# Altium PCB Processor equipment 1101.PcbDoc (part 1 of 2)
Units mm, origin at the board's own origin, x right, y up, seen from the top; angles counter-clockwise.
Board outline 129 x 113 mm, 4 copper layers (Top Layer, Signal Layer 1, Signal Layer 2, Bottom Layer), stack 0.778 mm thick; 199 components, 116 nets, 557 pads, 191 vias.
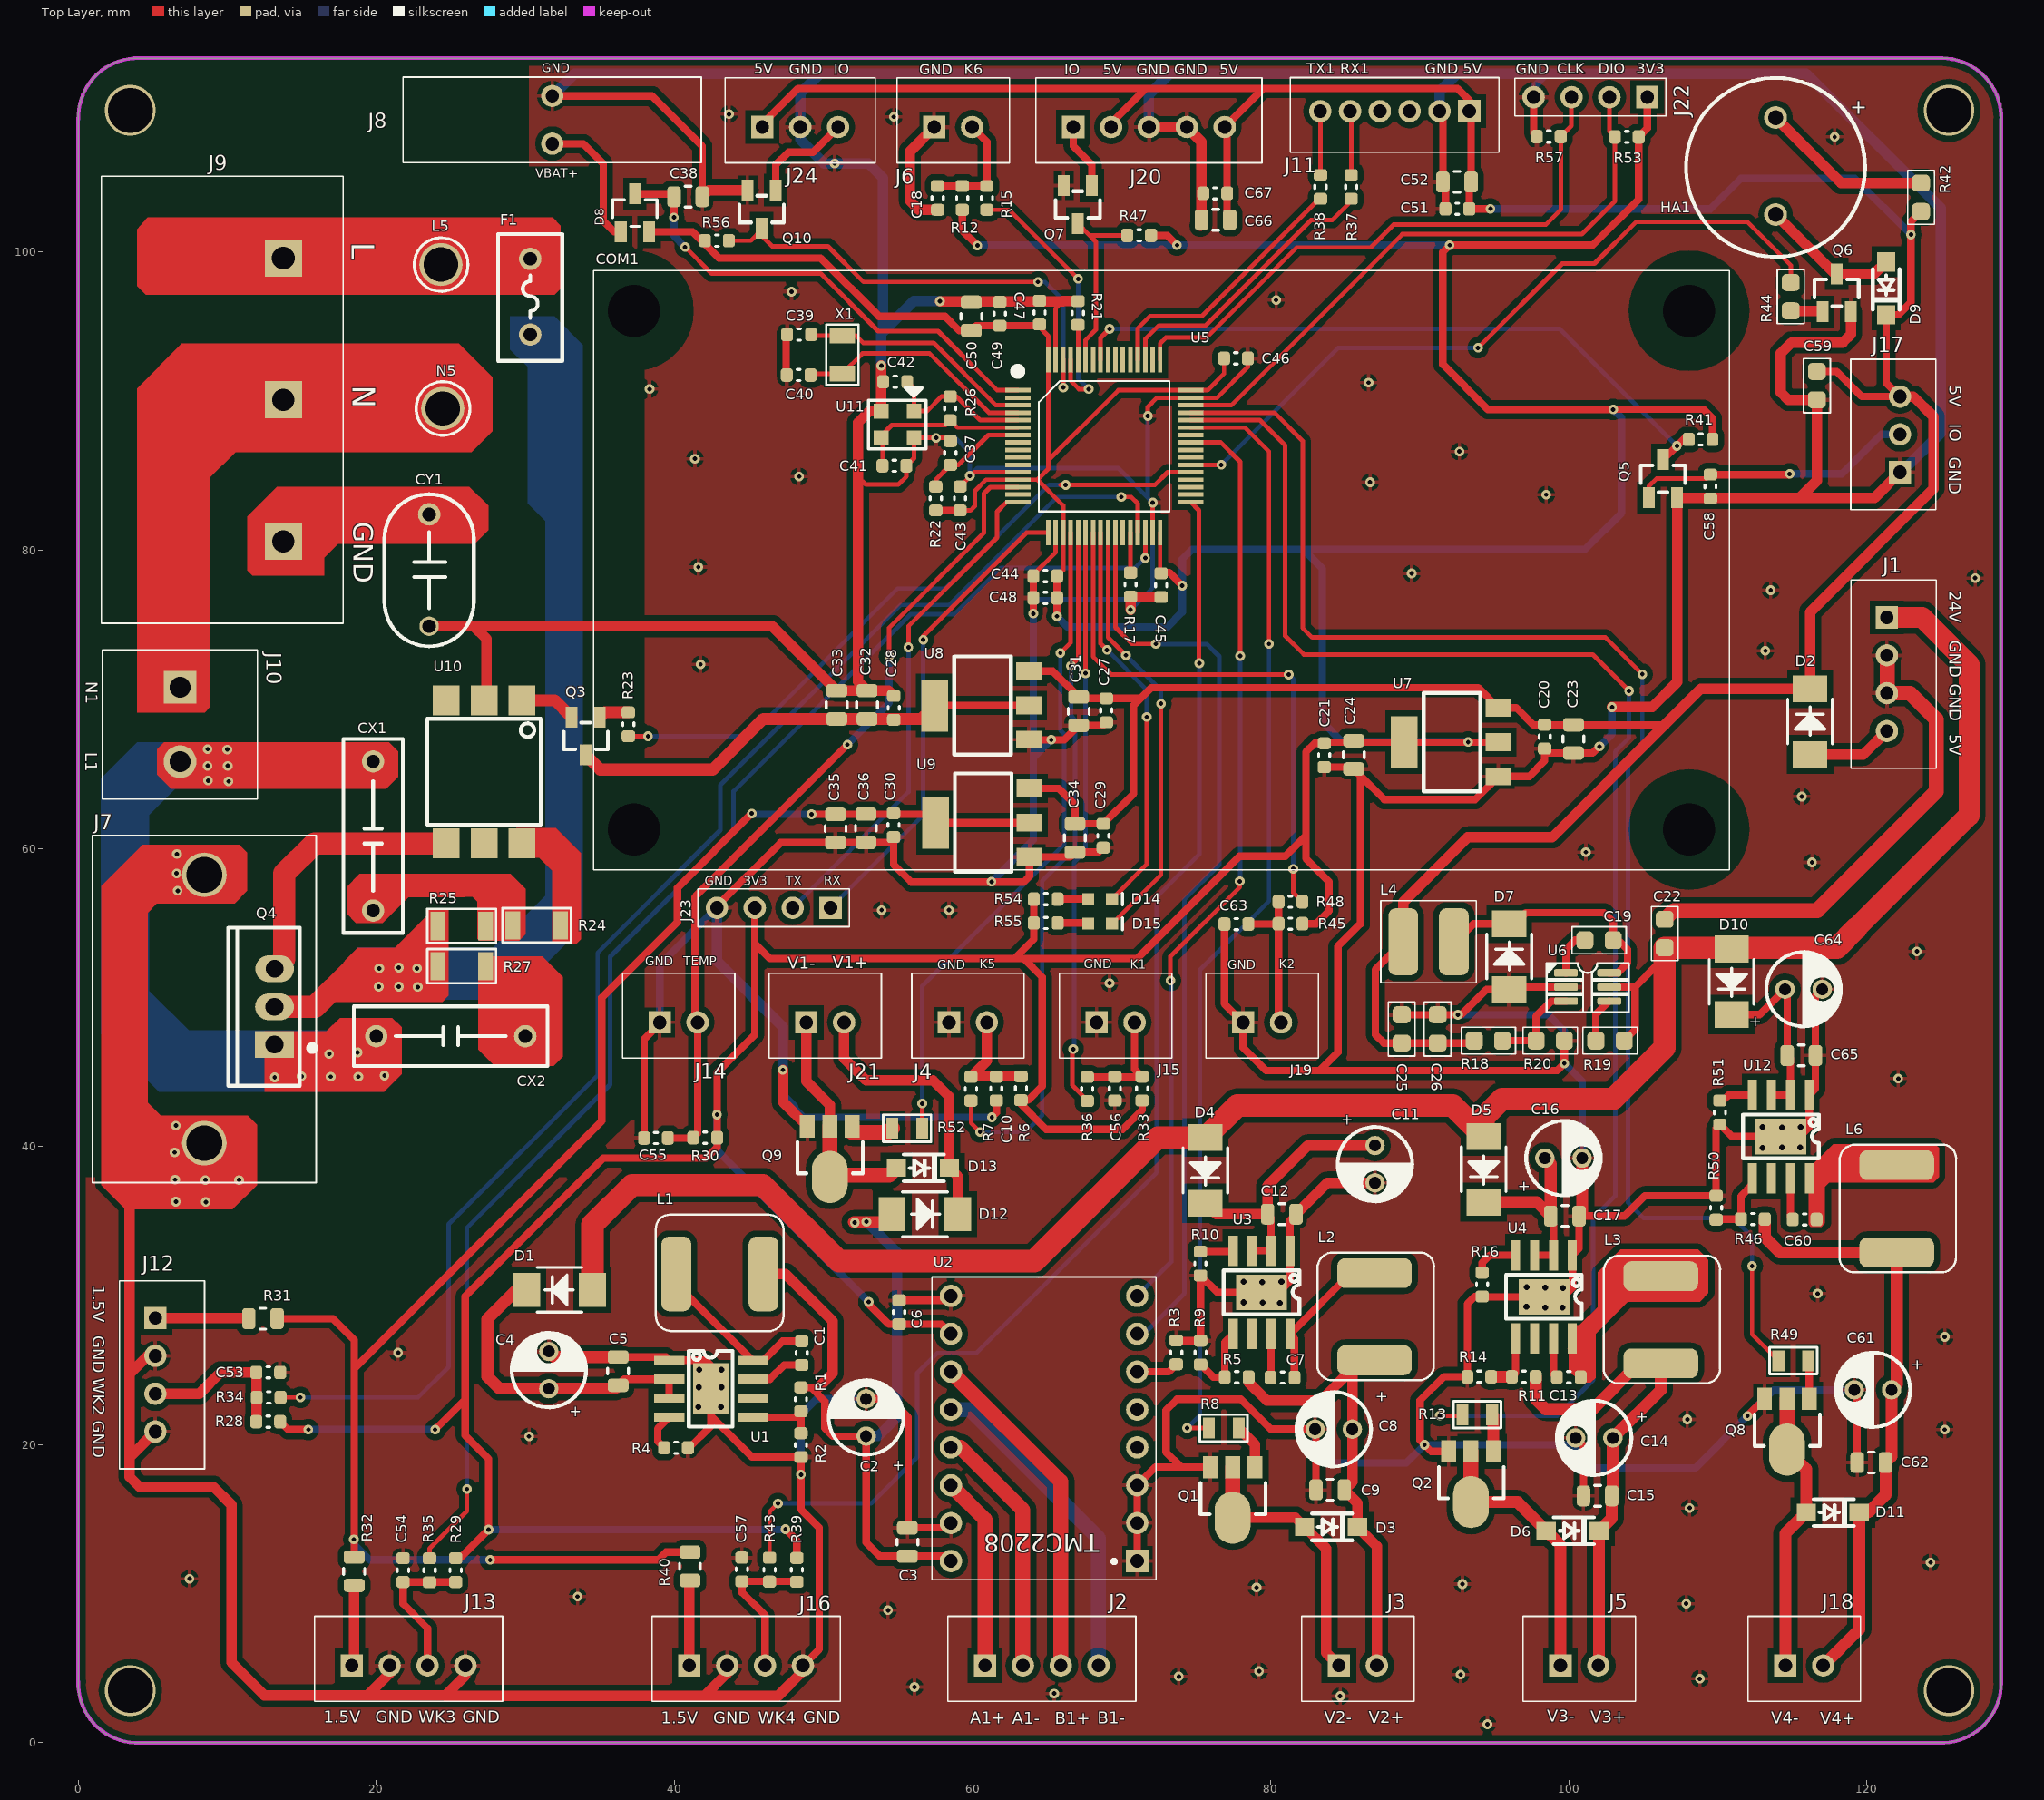
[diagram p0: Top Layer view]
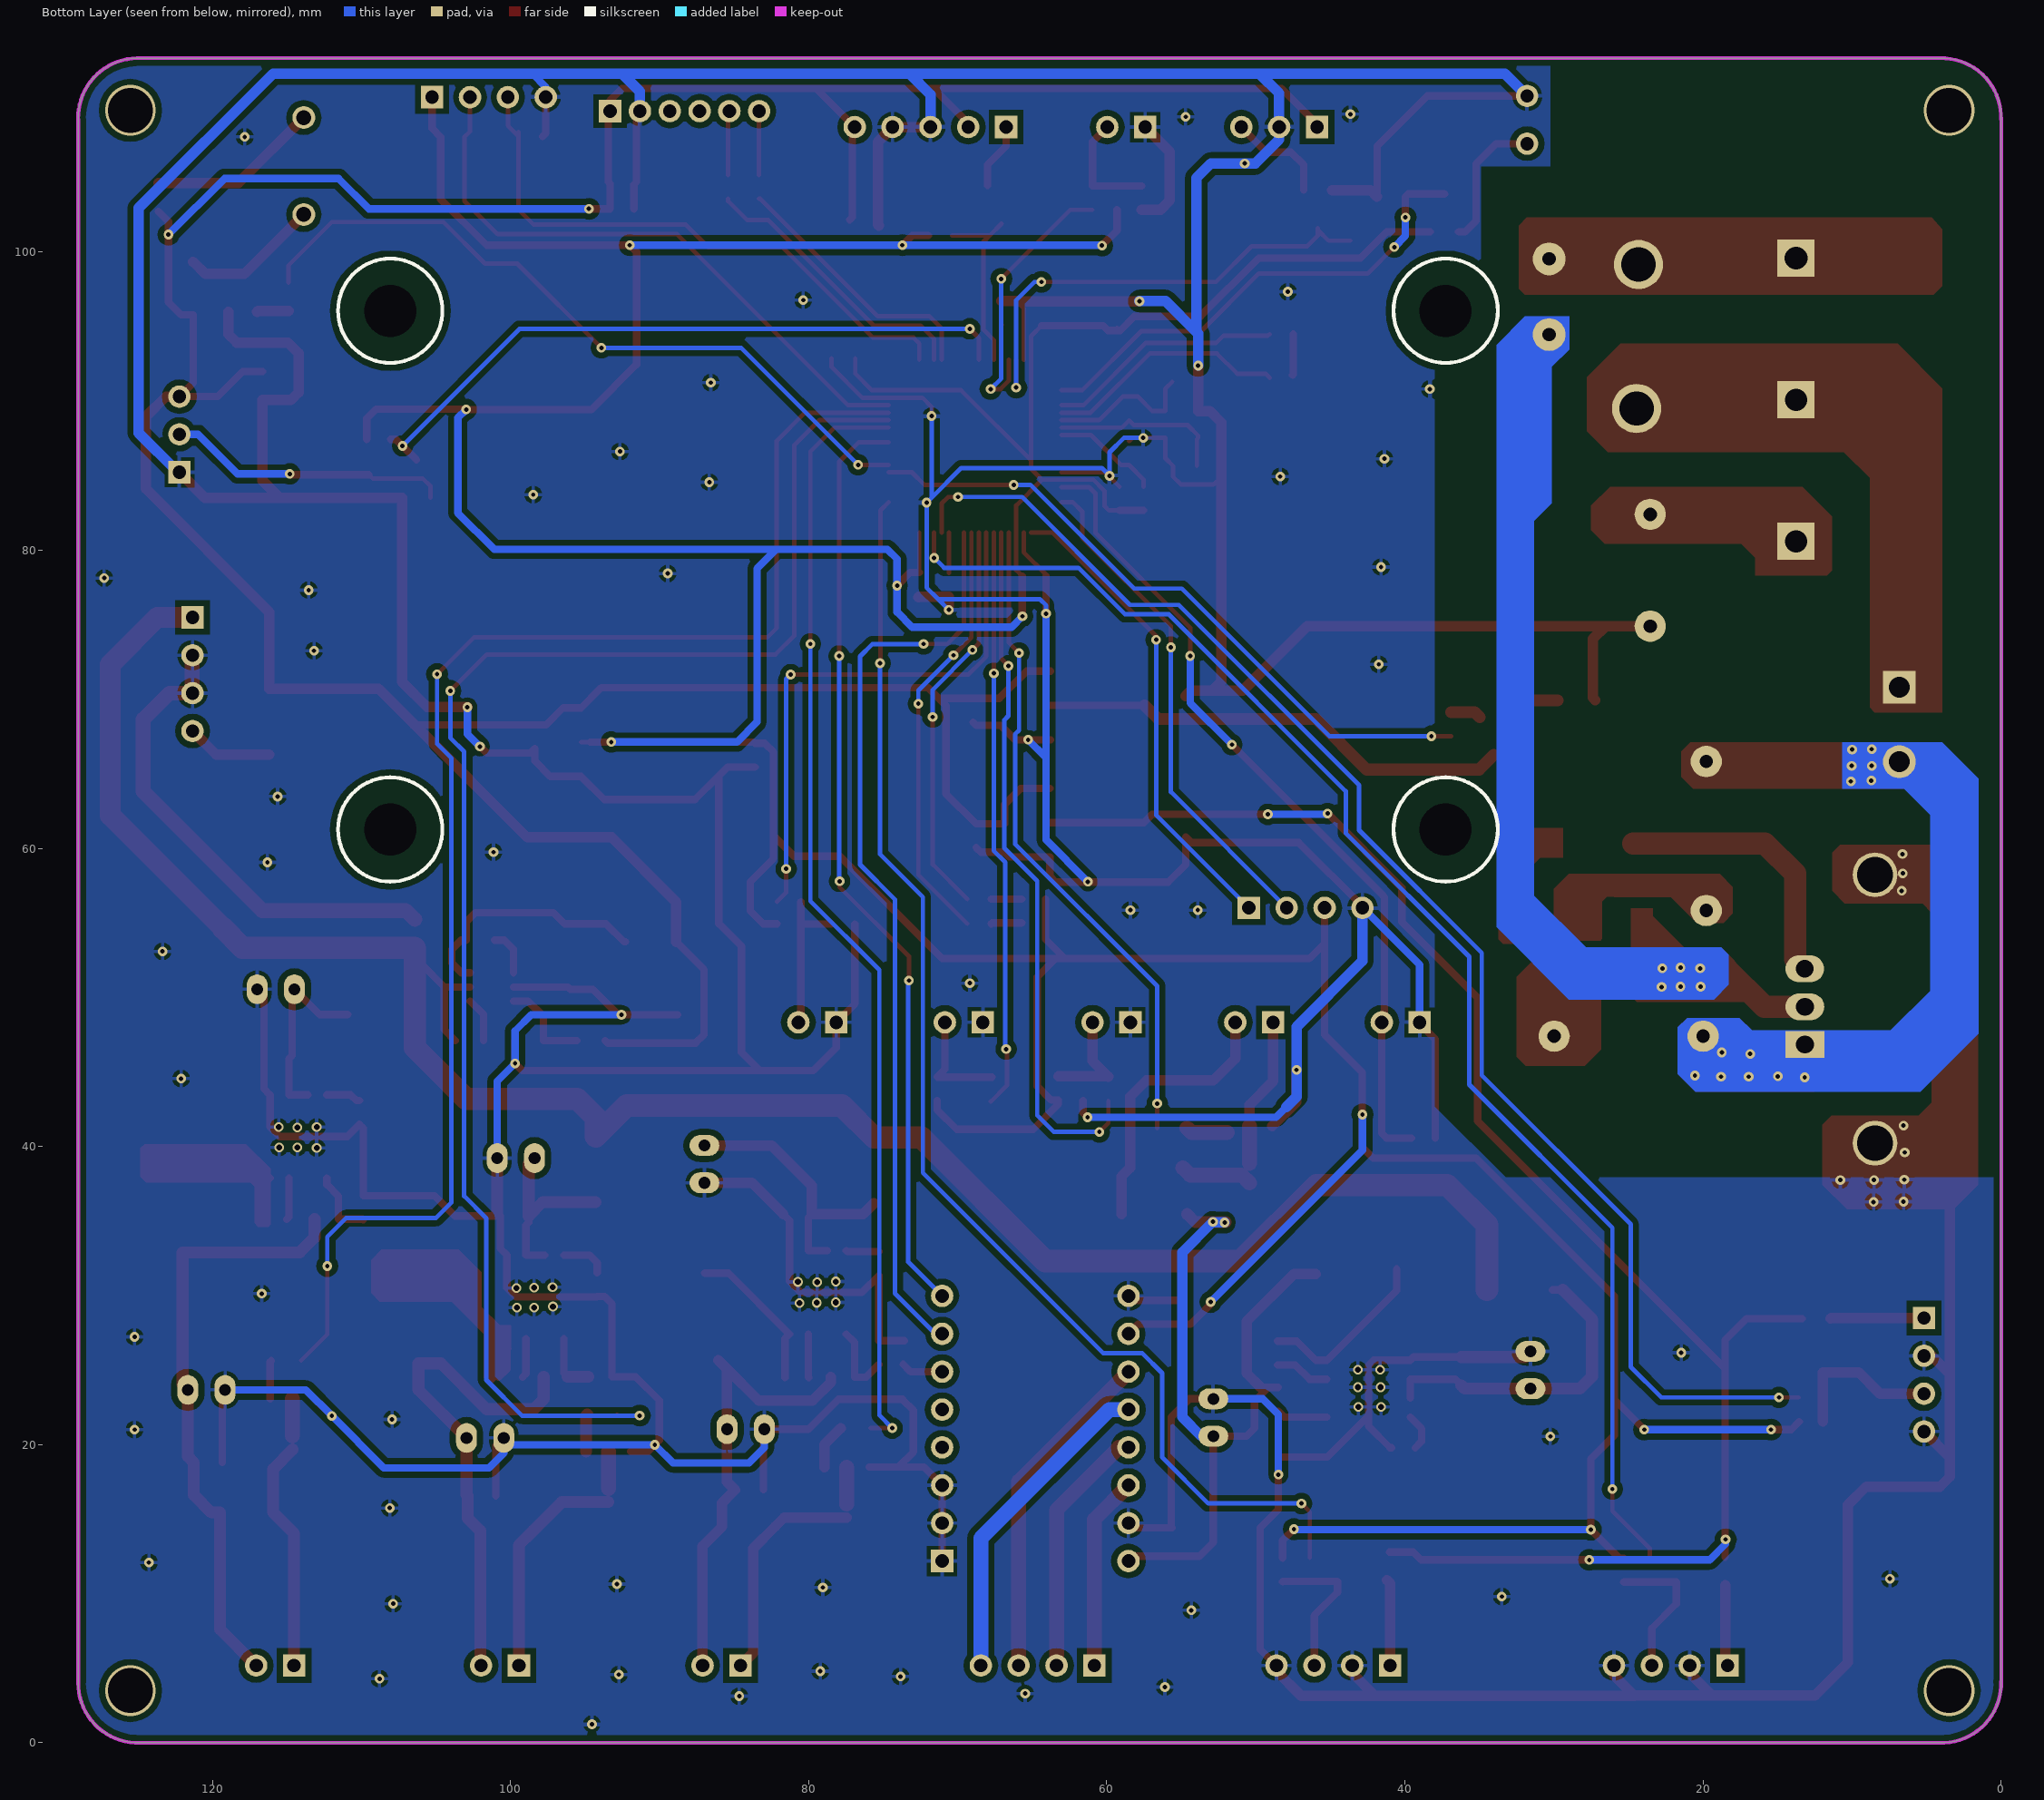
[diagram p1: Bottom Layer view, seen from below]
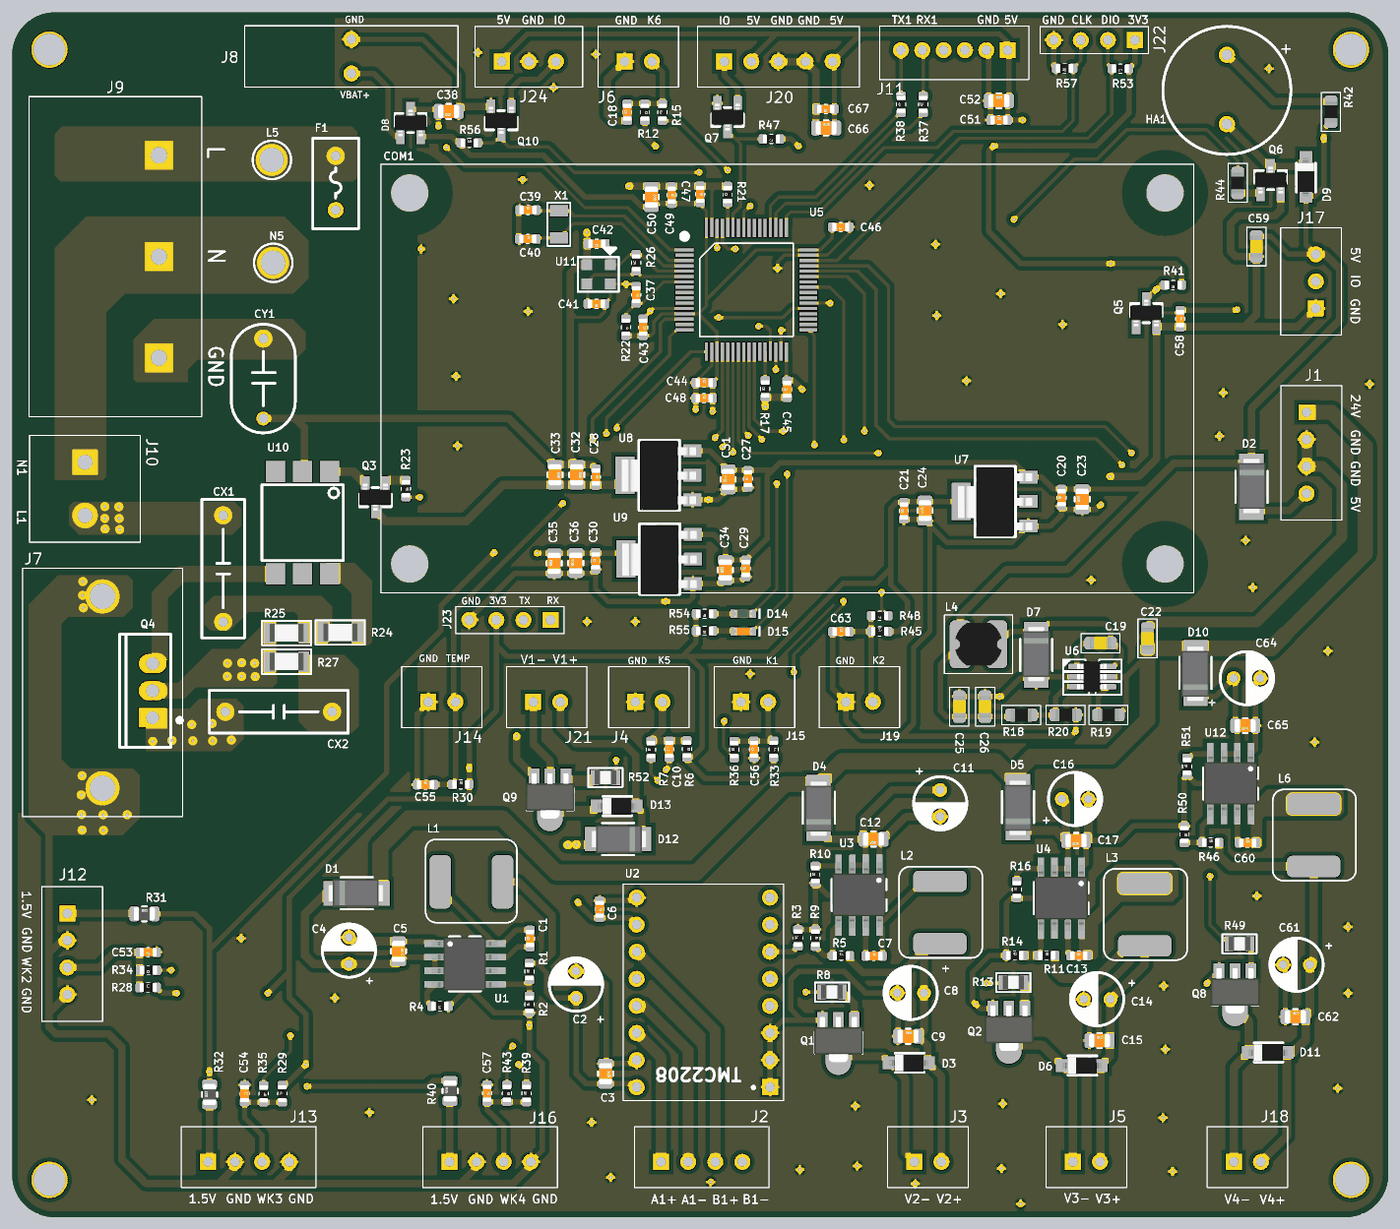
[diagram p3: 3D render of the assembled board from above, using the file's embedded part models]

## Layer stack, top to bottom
Top Solder: solder mask 0.0102, Solder Resist, Dk 3.5
Top Layer: signal copper 0.0356
Dielectric1: core 0.254, FR-4, Dk 4.2
Signal Layer 1: signal copper 0.036
Dielectric2: prepreg 0.127, Dk 4.2
Signal Layer 2: signal copper 0.036
Dielectric3: core 0.254, Dk 4.2
Bottom Layer: signal copper 0.0356
Bottom Solder: solder mask 0.0102, Solder Resist, Dk 3.5

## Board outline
3.807,0 cw(c3.998,3.991) 0.004,4.112 0,4.112 0,108.882 0.009,108.882 cw(c3.999,109.009) 4.089,113 125.063,113 cw(c125.005,109) 129.004,108.917 129,108.917 129,4.039 cw(c124.998,4) 124.852,0

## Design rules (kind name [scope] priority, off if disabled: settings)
Clearance [All] p1: gap=0.4
FabricationTestpoint [(IsPad And (OnTopLayer Or OnBottomLayer))] p1: side=3 testpointundercomponent=TRUE minsize=1.016 maxsize=2.54 preferedsize=1.524 minholesize=0 maxholesize=1.016 preferedholesize=0.813 testpointgrid=0.025 allowsidetop=TRUE allowsidebottom=TRUE usegrid=TRUE gridtolerance=0
PolygonConnect [All] p1: connectstyle=Relief reliefconductorwidth=0.254 reliefentries=4 polygonreliefangle="90 Angle" airgapwidth=0.254
RoutingVias [All] p1: holewidth=0.711 width=1.27 viastyle="Through Hole" minholewidth=0.711 minwidth=1.27 maxholewidth=0.711 maxwidth=1.27
SolderMaskExpansion [All] p1: expansion=0.102
Width [All] p1: maxlimit=5 minlimit=0.254 preferedwidth=0.254
29 further rules are at their usual default settings.

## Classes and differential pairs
component class "Processor equipment drive 1007": C51 C52 C53 C54 C55 C56 C57 C58 C59 C60 C61 C62 C63 C64 C65 C66 C67 D9 D10 D11 D12 D13 D14 D15 HA1 J11 J12 J13 J14 J15 J16 J17 J18 J19 J20 J21 J22 J23 J24 L6 Q5 Q6 Q7 Q8 Q9 Q10 Q11 R28 R29 R30 R31 R32 R33 R34 R35 R36 R37 R38 R39 R40 R41 R42 R43 R44 R45 R46 R47 R48 R49 R50 R51 R52 R53 R54 R55 R56 R57 U12
component class "Processor equipment control 1007": C19 C20 C21 C22 C23 C24 C25 C26 C27 C28 C29 C30 C31 C32 C33 C34 C35 C36 C37 C38 C39 C40 C41 C42 C43 C44 C45 C46 C47 C48 C49 C50 COM1 CX1 CX2 CY1 D7 D8 F1 J7 J8 J9 J10 L4 L5 N5 Q3 Q4 R17 R18 R19 R20 R21 R22 R23 R24 R25 R26 R27 U5 U6 U7 U8 U9 U10 U11 X1
component class "motor drive 1007": C1 C2 C3 C4 C5 C6 C7 C8 C9 C10 C11 C12 C13 C14 C15 C16 C17 C18 D1 D2 D3 D4 D5 D6 J1 J2 J3 J4 J5 J6 L1 L2 L3 Q1 Q2 R1 R2 R3 R4 R5 R6 R7 R8 R9 R10 R11 R12 R13 R14 R15 R16 U1 U2 U3 U4

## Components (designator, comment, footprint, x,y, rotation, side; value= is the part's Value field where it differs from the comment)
C1 "Capacitor NP" CAP_C_0603 48.539,26.137 r90 top locked
C2 "Capacitor POL" RB2.5/5_0.8 52.857,21.819 r270 top locked
C3 "Capacitor NP" CAP_C_0805 55.626,13.462 r270 top
C4 "Capacitor POL" RB2.5/5_0.8 31.572,24.999 r270 top locked
C5 "Capacitor NP" CAP_C_0805 36.22,24.928 r270 top locked
C6 "Capacitor NP" CAP_C_0603 55.067,28.88 r270 top
C7 "Capacitor NP" CAP_C_0603 80.795,24.496 r0 top locked
C8 "Capacitor POL" RB2.5/5_0.8 84.226,21.031 r0 top locked
C9 "Capacitor NP" CAP_C_0805 83.988,16.967 r0 top locked
C10 "Capacitor NP" CAP_C_0603 61.595,43.878 r90 top locked
C11 "Capacitor POL" RB2.5/5_0.8 86.995,38.811 r90 top locked
C12 "Capacitor NP" CAP_C_0805 80.747,35.458 r180 top locked
C13 "Capacitor NP" CAP_C_0603 99.997,24.521 r0 top locked
C14 "Capacitor POL" RB2.5/5_0.8 101.702,20.447 r0 top locked
C15 "Capacitor NP" CAP_C_0805 101.93,16.561 r0 top locked
C16 "Capacitor POL" RB2.5/5_0.8 99.639,39.218 r180 top locked
C17 "Capacitor NP" CAP_C_0805 99.736,35.331 r180 top locked
C18 "Capacitor NP" CAP_C_0603 57.658,103.632 r90 top locked
C19 "0.1uF" CAP_SMT_0805_T 102.027,53.833 r180 top locked
C20 "Capacitor NP" CAP_C_0603 98.374,67.488 r90 top locked
C21 "Capacitor NP" CAP_C_0603 83.591,66.243 r90 top locked
C22 "0.1uF" CAP_SMT_0805_T 106.426,54.28 r90 top locked
C23 "Capacitor NP" CAP_C_0805 100.305,67.335 r90 top locked
C24 "Capacitor NP" CAP_C_0805 85.573,66.269 r90 top locked
C25 "10uF" CAP_SMT_0805_T 88.788,47.884 r90 top locked
C26 "0.1uF" CAP_SMT_0805_T 91.201,47.884 r90 top locked
C27 "Capacitor NP" CAP_C_0603 68.971,69.251 r90 top locked
C28 "Capacitor NP" CAP_C_0603 54.712,69.418 r270 top locked
C29 "Capacitor NP" CAP_C_0603 68.768,60.843 r90 top locked
C30 "Capacitor NP" CAP_C_0603 54.697,61.555 r90 top locked
C31 "Capacitor NP" CAP_C_0805 67.117,69.2 r90 top locked
C32 "Capacitor NP" CAP_C_0805 52.923,69.626 r270 top locked
C33 "Capacitor NP" CAP_C_0805 50.891,69.626 r270 top locked
C34 "Capacitor NP" CAP_C_0805 66.863,60.691 r90 top locked
C35 "Capacitor NP" CAP_C_0805 50.81,61.326 r90 top locked
C36 "Capacitor NP" CAP_C_0805 52.842,61.351 r90 top locked
C37 "Capacitor NP" CAP_C_0603 58.507,86.51 r270 top locked
C38 "Capacitor NP" CAP_C_0805 40.919,103.708 r180 top
C39 "Capacitor NP" CAP_C_0603 48.362,94.463 r0 top locked
C40 "Capacitor NP" CAP_C_0603 48.336,91.745 r0 top
C41 "Capacitor NP" CAP_C_0603 54.76,85.659 r180 top locked
C42 "Capacitor NP" CAP_C_0603 54.811,91.298 r180 top locked
C43 "Capacitor NP" CAP_C_0603 59.157,83.464 r270 top locked
C44 "Capacitor NP" CAP_C_0603 64.872,78.257 r0 top locked
C45 "Capacitor NP" CAP_C_0603 72.644,77.648 r90 top locked
C46 "Capacitor NP" CAP_C_0603 77.673,92.862 r180 top locked
C47 "Capacitor NP" CAP_C_0603 64.491,95.936 r270 top locked
C48 "Capacitor NP" CAP_C_0603 64.872,76.797 r0 top locked
C49 "Capacitor NP" CAP_C_0603 61.824,95.86 r270 top
C50 "Capacitor NP" CAP_C_0805 59.919,95.682 r270 top
C51 "Capacitor NP" CAP_C_0603 92.52,102.895 r0 top locked
C52 "Capacitor NP" CAP_C_0805 92.497,104.699 r0 top locked
C53 "Capacitor NP" CAP_C_0603 12.751,24.841 r180 top locked
C54 "Capacitor NP" CAP_C_0603 21.793,11.582 r270 top locked
C55 "Capacitor NP" CAP_C_0603 38.76,40.564 r0 top locked
C56 "Capacitor NP" CAP_C_0603 69.545,43.879 r90 top locked
C57 "Capacitor NP" CAP_C_0603 44.526,11.62 r270 top
C58 "Capacitor NP" CAP_C_0603 109.499,84.264 r270 top locked
C59 "10uF" CAP_SMT_0805_T 116.637,91.034 r270 top locked
C60 "Capacitor NP" CAP_C_0603 115.811,35.103 r0 top locked
C61 "Capacitor POL" RB2.5/5_0.8 120.396,23.673 r0 top locked
C62 "Capacitor NP" CAP_C_0805 120.294,18.796 r0 top locked
C63 "Capacitor NP" CAP_C_0603 77.699,54.915 r0 top locked
C64 "Capacitor POL" RB2.5/5_0.8 115.748,50.546 r180 top locked
C65 "Capacitor NP" CAP_C_0805 115.595,46.101 r180 top locked
C66 "Capacitor NP" CAP_C_0805 76.302,102.159 r0 top
C67 "Capacitor NP" CAP_C_0603 76.276,103.937 r180 top
COM1 "HDR1X4" AC220v-24v 72.669,78.659 r180 top locked
CX1 "0.1UF 630V" C13*4*10_0.9 19.787,60.824 r90 top locked
CX2 "0.01UF 630V" C13*4*10_0.9 24.994,47.396 r180 top locked
CY1 "472" C9*6*7.5 23.546,78.65 r90 top locked
D1 "US1K" SMA-R 34.499,30.378 r180 top locked
D2 "US1K" SMA-R 116.18,66.294 r90 top locked
D3 "Diode Single" SOD123-R 82.271,14.478 r0 top locked
D4 "US1K" SMA-R 75.616,40.595 r270 top locked
D5 "US1K" SMA-R 94.285,40.665 r270 top locked
D6 "Diode Single" SOD123-R 98.476,14.224 r0 top locked
D7 "US1K" SMA-R 95.997,50.531 r90 top locked
D8 "BAT54C-7-F" SOT23-R-R 38.298,101.346 r270 top
D9 "Diode Single" SOD123-R 121.285,99.339 r270 top locked
D10 "US1K" SMA-R 110.922,53.244 r270 top locked
D11 "Diode Single" SOD123-R 115.926,15.443 r0 top locked
D12 "US1K" SMA-R 54.604,35.458 r0 top locked
D13 "Diode Single" SOD123-R 54.889,38.557 r0 top locked
D14 "LED_green" LED_0603_GREEN 68.555,56.591 r0 top locked
D15 "LED_red" LED_0603_RED 68.555,54.94 r0 top locked
F1 "6.3A/300V" FUSE_8.4*4.3_5.08_0.6 30.328,99.538 r270 top locked
HA1 "蜂鸣器" 蜂鸣器6.5mm 113.868,105.766 r270 top locked
J1 "HDR1X4" XH2.54mmX4P 121.336,71.679 r270 top locked
J2 "HDR1X4" XH2.54mmX4P 64.643,5.182 r0 top locked
J3 "2PIN" XH2.54mmX2P 85.845,5.182 r0 top locked
J4 "2PIN" XH2.54mmX2P 59.69,48.321 r0 top locked
J5 "2PIN" XH2.54mmX2P 100.704,5.182 r0 top locked
J6 "2PIN" XH2.54mmX2P 58.699,108.382 r0 top locked
J7 "2PIN" 散热器 8.469,49.22 r90 top locked
J8 "CR1220-2" CR2032-6 31.801,108.864 r90 top locked
J9 "3PIN" HB-9500-3P 13.767,90.089 r270 top locked
J10 "2PIN" DG/KF128-2P 6.833,68.307 r270 top locked
J11 "6PIN" HY2.0-6A 88.32,109.449 r180 top locked
J12 "HDR1X4" XH2.54mmX4P 5.182,24.685 r270 top locked
J13 "HDR1X4" XH2.54mmX4P 22.168,5.182 r0 top locked
J14 "2PIN" XH2.54mmX2P 40.284,48.321 r0 top locked
J15 "2PIN" XH2.54mmX2P 69.596,48.321 r0 top locked
J16 "HDR1X4" XH2.54mmX4P 44.809,5.182 r0 top locked
J17 "3PIN" XH2.54mm-3p 122.21,87.764 r90 top locked
J18 "2PIN" XH2.54mmX2P 115.792,5.182 r0 top locked
J19 "2PIN" XH2.54mmX2P 79.422,48.321 r0 top locked
J20 "Header 1x5" XH2.54MM-5P 71.831,108.382 r0 top locked
J21 "2PIN" XH2.54mmX2P 50.114,48.321 r0 top locked
J22 "HDR1X4" 2.54mmx4 105.258,110.388 r180 top locked
J23 "HDR1X4" 2.54mmx4 50.47,56.007 r180 top locked
J24 "3PIN" XH2.54mm-3p 48.438,108.382 r0 top locked
L1 "Inductor" 贴片电感 43.053,31.445 r180 top locked
L2 "Inductor" 贴片电感 86.97,28.579 r90 top locked
L3 "Inductor" 贴片电感 106.172,28.372 r90 top locked
L4 "100016336" 100016336_SS_B 90.589,53.731 r180 top locked
L5 "" PAD_1.8 24.333,99.157 r0 top locked
L6 "Inductor" 贴片电感 121.996,35.818 r90 top locked
N5 "" PAD_1.8 24.46,89.505 r0 top locked
Q1 "BCX56" SOT89-R-R#1 78.945,18.488 r90 top locked
Q2 "BCX56" SOT89-R-R#1 94.932,19.543 r90 top locked
Q3 "SS8050" SOT23-L-R 34.996,68.804 r90 top locked
Q4 "BT138-800E" TO-220-3_L10.0-W4.5-P2.54-L 13.175,49.373 r90 top locked
Q5 "PDTC143ZT" SOT23-L-R 105.364,83.515 r270 top locked
Q6 "SS8050" SOT23-L-R 117.018,95.987 r270 top locked
Q7 "PDTC143ZT" SOT23-L-R 68.006,104.455 r90 top
Q8 "BCX56" SOT89-R-R#1 116.129,23.063 r90 top locked
Q9 "BCX56" SOT89-R-R#2 51.918,41.351 r90 top locked
Q10 "PDTC143ZT" SOT23-L-R 46.797,104.15 r90 top
R1 "Resistor" RES_C_0603 48.489,23.038 r90 top locked
R2 "Resistor" RES_C_0603 48.489,19.964 r90 top locked
R3 "Resistor" RES_C_0603 73.66,26.187 r90 top
R4 "Resistor" RES_C_0603 40.107,19.787 r180 top locked
R5 "Resistor" RES_C_0603 77.722,24.521 r0 top locked
R6 "Resistor" RES_C_0603 63.246,43.904 r270 top locked
R7 "Resistor" RES_C_0603 59.893,43.866 r90 top locked
R8 "Resistor" 0805(2012)-R 75.851,21.107 r0 top locked
R9 "Resistor" RES_C_0603 75.296,26.172 r270 top locked
R10 "Resistor" RES_C_0603 75.286,32.144 r90 top locked
R11 "Resistor" RES_C_0603 96.975,24.547 r0 top locked
R12 "Resistor" RES_C_0603 59.309,103.632 r270 top locked
R13 "Resistor" 0805(2012)-R 92.854,22.007 r0 top locked
R14 "Resistor" RES_C_0603 93.99,24.547 r0 top locked
R15 "Resistor" RES_C_0603 60.96,103.632 r90 top locked
R16 "Resistor" RES_C_0603 94.183,30.734 r90 top locked
R17 "Resistor" RES_C_0603 70.597,77.684 r90 top locked
R18 "110k" RES_SMT_0805_T 94.6,47.092 r0 top locked
R19 "1k" RES_SMT_0805_T 102.764,47.102 r0 top locked
R20 "=" RES_SMT_0805_T 98.75,47.102 r180 top locked
R21 "Resistor" RES_C_0603 67.066,95.908 r90 top locked
R22 "Resistor" RES_C_0603 57.531,83.464 r270 top locked
R23 "Resistor" RES_C_0603 36.906,68.321 r270 top locked
R24 "1206 360R" 1206(3216)-R 32.359,54.834 r180 top locked
R25 "1206 470R" 1206(3216)-R 27.33,54.788 r180 top locked
R26 "Resistor" RES_C_0603 58.496,89.51 r90 top locked
R27 "1206 39R" 1206(3216)-R 27.33,52.095 r180 top locked
R28 "Resistor" RES_C_0603 12.751,21.539 r0 top locked
R29 "Resistor" RES_C_0603 25.324,11.582 r90 top locked
R30 "Resistor" RES_C_0603 42.062,40.589 r0 top locked
R31 "Resistor" RES_C_0805 12.395,28.448 r0 top
R32 "Resistor" RES_C_0805 18.517,11.506 r90 top locked
R33 "Resistor" RES_C_0603 71.374,43.879 r270 top locked
R34 "Resistor" RES_C_0603 12.776,23.165 r180 top locked
R35 "Resistor" RES_C_0603 23.571,11.57 r270 top locked
R36 "Resistor" RES_C_0603 67.691,43.853 r90 top locked
R37 "1K" RES_C_0603 85.395,104.369 r90 top
R38 "1K" RES_C_0603 83.337,104.369 r90 top
R39 "Resistor" RES_C_0603 48.209,11.595 r90 top
R40 "Resistor" RES_C_0805 41.046,11.836 r90 top
R41 "Resistor" RES_C_0603 108.839,87.427 r180 top locked
R42 "100000285" RES_SMT_0805_T 123.622,103.668 r90 top locked
R43 "Resistor" RES_C_0603 46.38,11.608 r270 top
R44 "100000285" RES_SMT_0805_T 114.884,97.003 r270 top
R45 "Resistor" RES_C_0603 81.326,54.94 r0 top locked
R46 "Resistor" RES_C_0603 112.344,35.128 r0 top locked
R47 "Resistor" RES_C_0603 71.171,101.117 r180 top
R48 "Resistor" RES_C_0603 81.326,56.413 r180 top locked
R49 "Resistor" 0805(2012)-R 114.053,25.629 r0 top locked
R50 "Resistor" RES_C_0603 109.88,35.89 r270 top locked
R51 "Resistor" RES_C_0603 110.134,42.278 r90 top locked
R52 "Resistor" 0805(2012)-R 56.617,41.224 r180 top locked
R53 "Resistor" RES_C_0603 103.886,107.721 r180 top
R54 "Resistor" RES_C_0603 64.91,56.591 r180 top locked
R55 "Resistor" RES_C_0603 64.91,54.991 r180 top locked
R56 "Resistor" RES_C_0603 42.85,100.762 r0 top
R57 "Resistor" RES_C_0603 98.654,107.747 r180 top
U1 "LM5164" SOIC-8-EP 42.443,23.749 r270 top locked
U2 "TMC2208" TMC2208 64.795,21.082 r180 top locked
U3 "LM5164" SOIC-8-EP 79.385,30.211 r180 top locked
U4 "LM5164" SOIC-8-EP 98.334,29.906 r180 top locked
U5 "GD32F303RCT6" LQFP64 63.03,90.724 r0 top locked
U6 "SY8292" SOT23_6 99.807,52.294 r0 top locked
U7 "MCP1754ST-5002ECB SOT-23A-3" SOT223-R 95.261,64.817 r0 top locked
U8 "MCP1754ST-5002ECB SOT-23A-3" SOT223-R 63.765,67.281 r0 top locked
U9 "MCP1754ST-5002ECB SOT-23A-3" SOT223-R 63.815,59.421 r0 top locked
U10 "MOC3020SM_C3014297" SOP-6_L7.1-W6.5-P2.54-LS10.1-BL 27.229,65.126 r180 top locked
U11 "8M晶振" S3225A 56.073,89.328 r180 top locked
U12 "LM5164" SOIC-8-EP 114.224,40.665 r180 top locked
X1 "X50328MSB2GI" X3215-2P晶振 51.257,93.116 r90 top

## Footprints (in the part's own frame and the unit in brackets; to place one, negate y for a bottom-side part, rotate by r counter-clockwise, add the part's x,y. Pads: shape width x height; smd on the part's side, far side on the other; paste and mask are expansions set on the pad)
2.54mmx4 [mm]
  rect 1.5x1.5 hole 0.9: 1(0,0)
  round 1.5 hole 0.9: 2(2.54,0) 3(5.08,0) 4(7.62,0)
  silkscreen extent -1.27,-1.27 8.89,1.27
0805(2012)-R [mm]
  rect 0.8x1.4 smd: 1(0,0) 2(2,0)
  silkscreen extent -0.6,-0.9 2.6,0.9, body extent 0,-0.65 2,0.66, height 0.73
1206(3216)-R [mm]
  rect 1x1.9 smd: 1(0,0) 2(3.2,0)
  silkscreen extent -0.7,-1.15 3.9,1.15, body extent 0,-0.84 3.2,0.82, height 0.53
100016336_SS_B [mm]
  rrect50% 2x4.5 smd: 1(-1.7,0) 2(1.7,0)
  silkscreen extent -3.2,-2.75 3.2,2.75, body extent -2.19,-2 2.19,2, height 4.2
AC220v-24v [mm]
  round 0 hole 3.5: 1(-35.4,-17.4) 2(-35.4,17.4) 3(35.4,17.4) 4(35.4,-17.4)
  silkscreen extent -38.1,-20.1 38.1,20.1
C9*6*7.5 [mm]
  round 1.3 / inner round 1.3 / far side round 2.1 hole 0.9: 1(-3.75,0)
  round 1.5 / inner round 1.5 / far side round 2.1 hole 0.9: 2(3.75,0)
  silkscreen extent -5.1,-3 5.1,3
C13*4*10_0.9 [mm]
  round 1.5 / inner round 1.5 / far side round 2.1 hole 0.9: 1(-5,0) 2(5,0)
  silkscreen extent -6.5,-2 6.5,2
CAP_C_0603 [mm] "Chip Capacitor, 2-Leads, Body 1.6x0.8mm, IPC Medium Density"
  rrect50% 0.8x0.9 smd: 1(-0.8,0) 2(0.8,0)
  silkscreen extent -0.1,-0.38 0.1,0.37, body extent -0.8,-0.4 0.8,0.4, height 0.3
CAP_C_0805 [mm] "Chip Capacitor, 2-Leads, Body 2.0x1.3mm, IPC Medium Density"
  rrect50% 0.9x1.4 smd: 1(-0.95,0) 2(0.95,0)
  silkscreen extent -0.2,-0.7 0.2,0.7, body extent -1,-0.62 1,0.63, height 0.78
CAP_SMT_0805_T [mm]
  rrect50% 1.14x1.2 smd: 1(-0.95,0) 2(0.95,0)
  silkscreen extent -1.82,-0.9 1.82,0.9, body extent -1,-0.6 1,0.6, height 0.5
CR2032-6 [mm]
  round 1.5 hole 0.9: 1(-1.6,0) 2(1.6,0)
  silkscreen extent -2.87,-10 2.87,10
DG/KF128-2P [mm]
  rect 2.2x2.2 hole 1.4: 1(-2.5,0)
  round 2.2 hole 1.4: 2(2.5,0)
  silkscreen extent -5,-5.2 5,5.2
FUSE_8.4*4.3_5.08_0.6 [mm]
  round 1.5 / inner round 1.5 / far side round 2.2 hole 0.9: 1(0,0) 2(5.08,0)
  silkscreen extent -1.66,-2.15 6.84,2.15
HB-9500-3P [mm]
  rect 2.5x2.5 hole 1.55: 1(-9.5,0)
  rect 2.5x2.5 hole 1.5: 2(0,0) 3(9.5,0)
  silkscreen extent -15,-12.2 15,4
HY2.0-6A [mm]
  rect 1.5x1.5 hole 0.9: 1(-5,0)
  round 1.5 hole 0.9: 2(-3,0) 3(-1,0) 4(1,0) 5(3,0) 6(5,0)
  silkscreen extent -7,-2.25 7,2.75
LED_0603_GREEN [mm] "LED chip 0603"
  rect 0.8x0.8 smd: 1(-0.8,0) 2(0.8,0)
  silkscreen extent 1.5,-0.4 1.5,0.4, body extent -0.81,-0.4 0.81,0.4, height 0.6
LED_0603_RED [mm] "LED chip 0603"
  rect 0.8x0.8 smd: 1(-0.8,0) 2(0.8,0)
  silkscreen extent 1.5,-0.4 1.5,0.4, body extent -0.81,-0.4 0.81,0.4, height 0.6
LQFP64 [mm] "10*10 0.5pitch"
  rect 1.7x0.3 smd: 1(0,0) 2(0,-0.5) 3(0,-1) 4(0,-1.5) 5(0,-2) 6(0,-2.5) 7(0,-3) 8(0,-3.5) 9(0,-4) 10(0,-4.5) 11(0,-5) 12(0,-5.5) 13(0,-6) 14(0,-6.5) 15(0,-7) 16(0,-7.5) 33(11.6,-7.5) 34(11.6,-7) 35(11.6,-6.5) 36(11.6,-6) 37(11.6,-5.5) 38(11.6,-5) 39(11.6,-4.5) 40(11.6,-4) 41(11.6,-3.5) 42(11.6,-3) 43(11.6,-2.5) 44(11.6,-2) 45(11.6,-1.5) 46(11.6,-1) 47(11.6,-0.5) 48(11.6,0)
  rect 0.3x1.7 smd: 17(2.05,-9.55) 18(2.55,-9.55) 19(3.05,-9.55) 20(3.55,-9.55) 21(4.05,-9.55) 22(4.55,-9.55) 23(5.05,-9.55) 24(5.55,-9.55) 25(6.05,-9.55) 26(6.55,-9.55) 27(7.05,-9.55) 28(7.55,-9.55) 29(8.05,-9.55) 30(8.55,-9.55) 31(9.05,-9.55) 32(9.55,-9.55) 49(9.55,2.05) 50(9.05,2.05) 51(8.55,2.05) 52(8.05,2.05) 53(7.55,2.05) 54(7.05,2.05) 55(6.55,2.05) 56(6.05,2.05) 57(5.55,2.05) 58(5.05,2.05) 59(4.55,2.05) 60(4.05,2.05) 61(3.55,2.05) 62(3.05,2.05) 63(2.55,2.05) 64(2.05,2.05)
  silkscreen extent -0.25,-8.13 10.18,1.52
PAD_1.8 [mm]
  round 2.9 / inner round 2.9 / far side round 3.3 hole 2.3 mask+0.05: 1(0,0)
  silkscreen extent -1.78,-1.8 1.82,1.8
RB2.5/5_0.8 [mm]
  round 1.3 / inner round 1.3 / far side oval 1.4x2 hole 0.8: 1(1.25,0) 2(-1.25,0)
  silkscreen extent -2.5,-2.5 2.5,2.5
RES_C_0603 [mm] "Chip Resistor, 2-Leads, Body 1.6x0.8mm, IPC Medium Density"
  rrect50% 0.8x0.9 smd: 1(-0.8,0) 2(0.8,0)
  silkscreen extent -0.1,-0.38 0.1,0.38, body extent -0.8,-0.4 0.8,0.4, height 0.3
RES_C_0805 [mm] "Chip Resistor, 2-Leads, Body 2.0x1.3mm, IPC Medium Density"
  rrect50% 0.9x1.4 smd: 1(-0.95,0) 2(0.95,0)
  silkscreen extent -0.2,-0.7 0.2,0.7, body extent -1,-0.63 1,0.63, height 0.78
RES_SMT_0805_T [mm]
  rrect50% 1.14x1.2 smd: 1(-0.95,0) 2(0.95,0)
  silkscreen extent -1.82,-0.9 1.82,0.9, body extent -1,-0.61 1,0.59, height 0.49
S3225A [mm]
  rect 1x1 smd mask+0.025: 1(0,0) 2(2.2,0) 3(2.2,1.8) 4(0,1.8)
  silkscreen extent -0.8,-1.55 3.05,2.52
SMA-R [mm]
  rect 1.8x2.3 smd: 1(0,0) 2(4.4,0)
  silkscreen extent 0.7,-1.5 3.7,1.5, body extent -0.32,-1.31 4.88,1.29, height 2.4
SOD123-R [mm]
  rect 1.3x1.2 smd: 1(0,0) 2(3.556,0)
  silkscreen extent 0.5,-0.9 3.2,0.9, body extent -0.05,-0.81 3.65,0.79, height 1.27
SOIC-8-EP [mil]
  rect 133.86x94.49 smd mask+1: 0(0,0)
  rect 24x80 smd mask+1: 1(-75,-110) 2(-25,-110) 3(25,-110) 4(75,-110) 5(75,110) 6(25,110) 7(-25,110) 8(-75,110)
  silkscreen extent -100,-58 100,58, body extent -99,-123 98,121, height 73
SOP-6_L7.1-W6.5-P2.54-LS10.1-BL [mm]
  rect 1.8x2 smd: 1(-2.54,-4.8) 2(0,-4.8) 3(2.54,-4.8) 4(2.54,4.8) 5(0,4.8) 6(-2.54,4.8)
  silkscreen extent -3.81,-3.56 3.81,3.55
SOT23-L-R [mm]
  rect 1.4x0.8 smd: 1(0,0) 2(0,1.9) 3(-2.55,0.95)
  silkscreen extent -2.18,-0.54 -0.38,2.43, body extent -2.53,-0.55 -0.03,2.45, height 1.05
SOT23-R-R [mm]
  rect 1.4x0.8 smd: 1(0,0) 2(0,-1.9) 3(-2.55,-0.95)
  silkscreen extent -2.18,-2.44 -0.38,0.53, body extent -2.53,-2.45 -0.03,0.55, height 1.05
SOT23_6 [mm]
  rrect50% 1.6x0.5 smd: 1(0,-0.65) 2(0,-1.6) 3(0,-2.55) 4(2.9,-2.55) 5(2.9,-1.6) 6(2.9,-0.65)
  silkscreen extent -1.32,-3.3 4.2,0.04, body extent 0.01,-3.06 2.81,-0.16, height 1.17
SOT89-R-R#1 [mm]
  rect 1.5x1 smd: 1(0,3) 2(0,1.5) 3(0,0)
  oval 3.5x2.4 smd: 2(-3.4,1.5)
  Top Layer lines w1: -2.487,1.5 0,1.5
  silkscreen extent -3.15,-0.71 -1.05,3.66, body extent -3.96,-0.82 0.29,3.78, height 1.59
SOT89-R-R#2 [mm]
  rect 1.5x1 smd: 1(0,3) 2(0,1.5) 3(0,0)
  oval 3.5x2.4 smd: 2(-3.4,1.5)
  Top Layer lines w1: -2.487,1.5 -0.758,1.5 0,1.5
  silkscreen extent -3.15,-0.71 -1.05,3.66, body extent -3.96,-0.82 0.29,3.78, height 1.59
SOT223-R [mm]
  rect 1.7x1.2 smd: 1(0,0) 2(0,2.3) 3(0,4.6)
  rect 1.8x3.5 smd: 2(-6.3,2.3)
  silkscreen extent -5,-1 -1.2,5.6, body extent -6.61,-0.99 0.35,5.51, height 1.7
TMC2208 [mm]
  rect 1.5x1.5 hole 0.9: 1(-6.25,8.89)
  round 1.5 hole 0.9: 2(-6.25,6.35) 3(-6.25,3.81) 4(-6.25,1.27) 5(-6.25,-1.27) 6(-6.25,-3.81) 7(-6.25,-6.35) 8(-6.25,-8.89) 9(6.25,-8.89) 10(6.25,-6.35) 11(6.25,-3.81) 12(6.25,-1.27) 13(6.25,1.27) 14(6.25,3.81) 15(6.25,6.35) 16(6.25,8.89)
  silkscreen extent -7.52,-10.16 7.52,10.16
TO-220-3_L10.0-W4.5-P2.54-L [mm]
  rect 1.8x2.6 hole 1.2: 1(-2.54,0.005)
  oval 1.8x2.6 hole 1.2: 2(0,0.005)
  oval 1.8x2.6 hole 1.2 copper offset 0,0: 3(2.54,-0.005)
  silkscreen extent -5.3,-2.73 5.3,3.09
X3215-2P晶振 [mm]
  rect 1.05x1.7 smd: 1(-1.275,0) 2(1.275,0)
  silkscreen extent -2.03,-1.08 2.03,1.08
XH2.54mm-3p [mm]
  rect 1.5x1.5 hole 0.9: 1(-2.54,0)
  round 1.5 hole 0.9: 2(0,0) 3(2.54,0)
  silkscreen extent -5.04,-2.4 5.04,3.3
XH2.54MM-5P [mm]
  rect 1.5x1.5 hole 0.9: 1(-5.08,0)
  round 1.5 hole 0.9: 2(-2.54,0) 3(0,0) 4(2.54,0) 5(5.08,0)
  silkscreen extent -7.58,-2.4 7.58,3.3
XH2.54mmX2P [mm]
  rect 1.5x1.5 hole 0.9: 1(-1.27,0)
  round 1.5 hole 0.9: 2(1.27,0)
  silkscreen extent -3.77,-2.4 3.77,3.3
XH2.54mmX4P [mm]
  rect 1.5x1.5 hole 0.9: 1(-3.81,0)
  round 1.5 hole 0.9: 2(-1.27,0) 3(1.27,0) 4(3.81,0)
  silkscreen extent -6.31,-2.4 6.31,3.3
散热器 [mm]
  round 3 hole 2.4: 1(-9,0) 2(9,0)
  silkscreen extent -11.65,-7.5 11.65,7.5
蜂鸣器6.5mm [mm]
  round 1.524 hole 1: 1(-3.25,0) 2(3.25,0)
  silkscreen extent -5.91,-6 6.09,6
贴片电感 [mm]
  rrect50% 2x5 smd mask+0.102: 1(-2.925,0) 2(2.925,0)
  silkscreen extent -4.27,-3.98 4.3,3.84

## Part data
C1 C6 C7 C10 C13 C18 C20 C21 C27 C28 C29 C30 C37 C39 C40 C41 C42 C43 C44 C45 C46 C47 C48 C49 C51 C53 C54 C55 C56 C57 C60 C63: library part CAP2016, "Capacitor"
C2 C4 C8 C11 C14 C16 C61 C64: library part CAP2449, "Capacitor"
C3 C5 C9 C12 C15 C17 C23 C24 C31 C32 C33 C34 C35 C36 C38 C50 C52 C62 C65 C66: library part CAP1211, "Capacitor"
C19 C22 C25 C26 C59: library part 100000401, "R_贴片电容_104K_50V_X7R_0805"
C58 C67: library part CAP1116
CX1 CX2: library part 4711101100299, "电容"
CY1: library part 4711140200471
D1 D2 D4 D5 D7 D10 D12: library part 4715102500027, "二极管"
D3 D6 D9 D11 D13: library part DIODE0165
D14: library part DIODE1155, "LED"
D15: library part DIODE1058, "LED"
F1: library part 4621200700163, "保险丝"
J20: library part CON0416
L1 L2 L3 L6: library part IND1145
L4: "R贴片工字电感4*4_10uHM_21T_0.21*148mΩ"
L5 N5: library part 1pinx1.8mm
Q1 Q2 Q8 Q9: library part 4715205500100, "ECB"
Q3 Q6: library part 4715205500018, "BEC"
Q5 Q7 Q10: "4.7k+47k NPN"
R1 R2 R5 R9 R11 R14 R17 R21 R46 R50: library part RSMT0139
R3 R4 R8 R10 R13 R16 R30 R49 R51 R52: library part RSMT0349
R6 R7 R12 R15 R28 R29 R33 R34 R35 R36 R39 R43 R45 R48 R53 R57: library part RES1406
R18: library part 100000285, "R_片阻_100KJ_1/8W_±100PPM/℃_0805"
R19: library part 100000289, "R_片阻_1KJ_1/8W_±100PPM/℃_0805"
R20: library part 100025954, "R_片阻_12KF_1/8W_±100PPM/℃_0805"
R22 R23 R26: library part RES1051
R24 R25 R27: library part 4712101500957, "Resistor"
R31 R32 R40: library part RSMT0522
R37 R38: library part RES1406, "Resistor"
R41 R47 R56: library part RES1130
R42 R44: "R_片阻_100KJ_1/8W_±100PPM/℃_0805"
R54 R55: library part RES1133
U5: library part GD32F303RxT6
U7 U8 U9: library part MIC9094, "LDO"

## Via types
v1: diameter 0.65, hole 0.3, Top Layer to Bottom Layer, 163 vias
v2: diameter 0.65, hole 0.4, Top Layer to Bottom Layer, 24 vias
v3: diameter 3.4, hole 3, Top Layer to Bottom Layer, 4 vias

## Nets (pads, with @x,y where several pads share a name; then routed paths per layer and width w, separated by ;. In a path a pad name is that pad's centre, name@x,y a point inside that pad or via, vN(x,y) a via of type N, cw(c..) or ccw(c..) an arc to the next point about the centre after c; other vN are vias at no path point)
5V: C20.2 C23.2 C25.1 C26.1 C27.2 C29.2 C31.2 C34.2 C51.2 C52.2 C59.1 C66.2 C67.1 D2.2 D9.2 J11.1 J17.3 J20.2 J20.5 J24.1 L4.2 R18.1 R42.1 U7.3 U8.3 U9.3 | length 257.7
  Top Layer w0.5: J24.1@45.898,108.382 45.898,108.585 48.285,110.973 71.628,110.973 ; U8.3@63.765,71.881 65.386,71.881 C31.2@67.117,70.15 67.216,70.051 C27.2@68.971,70.051 71.27,70.051 ; U9.3@63.815,64.021 65.773,64.021 66.863,62.931 C34.2@66.863,61.641 68.766,61.641 C29.2@68.768,61.643 70.79,63.665 70.79,69.571 71.27,70.051 ; J20.2@69.291,108.382 69.291,108.636 71.628,110.973 ; C66.2@77.252,102.159 77.076,102.334 C67.1@77.076,103.937 77.076,108.217 J20.5@76.911,108.382 79.502,110.973 ; L4.2@88.889,53.731 87.02,51.863 87.02,47.498 87.585,46.934 C25.1@88.788,46.934 C26.1@91.201,46.934 93.492,46.934 R18.1@93.65,47.092 ; v1(94.742,102.895) C51.2@93.32,102.895 93.32,104.572 C52.2@93.447,104.699 93.447,109.322 J11.1@93.32,109.449 93.32,110.185 92.532,110.973 79.502,110.973 ; 106.436,68.285 C23.2@100.305,68.285 97.602,68.285 96.47,69.417 U7.3@95.261,69.417 93.914,70.764 71.984,70.764 71.27,70.051 ; C59.1@116.637,91.984 117.973,91.984 119.653,90.304 J17.3@122.21,90.304 121.285,91.228 D9.2@121.285,95.783 122.098,95.783 122.949,96.634 v1(122.949,101.168) 122.949,102.044 R42.1@123.622,102.718 ; 71.628,110.973 79.502,110.973
  Top Layer w0.7: L4.2@88.889,53.731 88.889,56.402 93.218,60.731 98.882,60.731 106.436,68.285 108.845,70.694 D2.2@116.18,70.694 116.18,75.844 124.46,84.125 124.46,88.951 123.107,90.304 J17.3@122.21,90.304
  Bottom Layer w0.5: v1(94.742,102.895) 109.499,102.895 111.531,104.927 119.189,104.927 v1(122.949,101.168)
24V: C22.1 D1.1 D4.1 D5.1 D10.1 J1.1 R19.2 U6.5 | length 143.9
  Top Layer w0.5: U6.5@102.707,50.694 104.44,50.694 ; R19.2@103.714,47.102 104.44,47.828 104.44,50.694 ; 106.426,52.207 105.954,52.207 104.44,50.694
  Top Layer w1.4: 119.291,54.648 126.848,62.205 126.848,72.339 123.698,75.489 J1.1@121.336,75.489
  Top Layer w1.5: D1.1@34.499,30.378 34.499,34.753 37.16,37.414 45.923,37.414 51.029,32.309 64.135,32.309 72.421,40.595 D4.1@75.616,40.595 77.769,42.748 92.202,42.748 D5.1@94.285,40.665 94.285,41.935 95.529,43.18 102.972,43.18 106.426,46.634 106.426,52.207 C22.1@106.426,53.33 117.973,53.33 119.291,54.648
+1.2V: C28.2 C32.2 C33.2 Q3.3 U8.2 | length 31.9
  Top Layer w0.5: U8.2@57.465,69.581 U8.2@63.765,69.581
  Top Layer w0.8: Q3.3@34.046,66.254 35.022,65.278 42.57,65.278 45.969,68.676 C33.2@50.891,68.676 C32.2@52.923,68.676 56.56,68.676 U8.2@57.465,69.581
+1.5V: C30.2 C35.2 C36.2 R31.2 R32.2 R40.2 U9.2 | length 111
  Top Layer w0.5: R31.2@13.345,28.448 17.094,28.448 18.517,27.026 18.517,25.095 ; R32.2@18.517,12.456 18.517,25.095 ; v1(27.635,12.268) 38.903,12.268 39.421,12.786 R40.2@41.046,12.786 ; v1(45.187,62.332) 40.208,57.353 40.208,55.067 35.128,49.987 35.128,41.707 18.517,25.095 ; v1(49.2,62.281) 50.806,62.281 C35.2@50.81,62.276 52.842,62.276 56.96,62.276 U9.2@57.515,61.721 U9.2@63.815,61.721
  Bottom Layer w0.5: v1(18.491,13.64) 18.491,13.335 19.558,12.268 v1(27.635,12.268) ; v1(45.187,62.332) 45.212,62.332 45.268,62.276 45.272,62.281 v1(49.2,62.281)
+3V3: C6.2 C21.2 C24.2 C43.2 C44.2 C45.2 C46.2 C47.2 C48.2 C49.2 C50.2 D8.1 J22.1 J23.3 R6.2 R12.2 R22.2 R28.2 R29.2 R30.2 R33.2 R39.2 R41.1 R45.2 R47.1 R53.1 R54.2 R55.2 R56.1 U2.10 U5.13 U5.19 U5.32 U5.48 U5.64 U7.2 | length 447.3
  Top Layer w0.3: C43.2@59.157,82.664 59.855,82.664 60.147,82.956 60.147,83.972 60.898,84.724 U5.13@63.03,84.724 64.349,84.724 ; C47.2@64.376,95.06 65.08,94.356 U5.64@65.08,92.774 65.08,86.03 ; C44.2@65.672,78.257 66.08,78.666 U5.19@66.08,81.174 66.08,82.993 64.349,84.724 ; C45.2@72.58,78.495 U5.32@72.58,81.174 ; C46.2@76.873,92.862 76.873,91.834 75.763,90.724 U5.48@74.63,90.724 69.774,90.724 65.08,86.03 ; U7.2@94.666,67.117 U7.2@95.261,67.117 ; 64.349,84.724 64.353,84.724 65.08,85.451 65.08,86.03
  Top Layer w0.5: R28.2@13.551,21.539 14.084,21.006 v1(15.443,21.006) ; v1(23.952,21.006) 25.959,23.012 ; R29.2@25.324,12.382 25.616,12.382 v1(27.534,14.3) 27.534,19.05 25.959,20.625 25.959,23.012 ; D8.1@38.298,101.346 41.224,101.346 42.977,99.593 49.809,99.593 53.721,95.682 58.152,95.682 59.102,94.732 C50.2@59.919,94.732 60.246,95.06 C49.2@61.824,95.06 C47.2@64.376,95.06 ; J23.3@45.39,56.007 45.39,53.619 ; v1(47.447,14.326) 48.209,13.564 R39.2@48.209,12.395 ; v1(53.035,29.566) 53.035,29.426 54.381,28.08 C6.2@55.067,28.08 57.898,28.08 U2.10@58.545,27.432 ; R22.2@57.531,82.664 C43.2@59.157,82.664 ; R12.2@59.309,102.832 59.309,101.448 v1(60.325,100.432) ; R54.2@64.11,56.591 R55.2@64.11,54.991 64.11,53.899 62.814,52.603 ; v1(65.659,75.565) 65.672,75.578 C48.2@65.672,76.797 C44.2@65.672,78.257 ; R33.2@71.374,43.079 71.374,42.443 70.079,41.148 64.922,41.148 63.246,42.824 R6.2@63.246,43.104 63.729,43.104 64.668,44.044 64.668,51.359 63.424,52.603 ; R47.1@71.971,101.117 73.05,101.117 v1(73.711,100.457) ; C45.2@72.58,78.495 73.194,78.495 v1(74.066,77.622) ; R45.2@82.126,54.94 83.058,54.94 83.922,55.804 83.922,57.76 82.372,59.309 82.372,60.858 ; U7.2@94.666,67.117 U7.2@88.961,67.117 83.665,67.117 C21.2@83.591,67.043 82.944,67.043 82.372,66.472 82.372,60.858 ; v1(102.972,89.433) 94.564,89.433 91.542,92.456 91.542,100 v1(91.999,100.457) 101.6,100.457 104.686,103.543 R53.1@104.686,107.721 105.258,108.293 J22.1@105.258,110.388 ; v1@102.972,89.459 109.017,89.459 109.639,88.837 R41.1@109.639,87.427 ; 25.959,23.012 25.959,29.947 35.23,39.218 42.139,39.218 42.862,39.941 R30.2@42.862,40.589 42.862,44.971 45.39,47.498 45.39,53.619 ; 45.39,53.619 46.406,52.603 62.814,52.603 ; 62.814,52.603 63.424,52.603 ; 63.424,52.603 71.044,52.603 77.902,59.461 80.975,59.461 82.372,60.858
  Bottom Layer w0.5: v1(15.443,21.006) v1(23.952,21.006) ; v1(27.534,14.3) 47.422,14.3 v1(47.447,14.326) ; v1(42.85,42.139) 42.85,39.751 v1(53.035,29.566) ; v1(60.325,100.432) 60.35,100.457 v1(73.711,100.457) v1(91.999,100.457) ; v1(65.659,75.565) 66.396,74.828 73.05,74.828 74.066,75.844 v1(74.066,77.622) 74.066,79.4 74.727,80.061 82.169,80.061 ; v1(93.243,67.132) 84.811,67.132 83.464,68.478 83.464,78.765 82.169,80.061 ; v1(102.972,89.433) 103.53,88.875 103.53,82.499 101.092,80.061 82.169,80.061
+12V1: C2.1 C3.2 D12.1 L1.1 R1.2 U2.16 | length 51.6
  Top Layer w0.5: R1.2@48.489,23.838 49.162,23.838 ; 49.67,23.838 49.162,23.838 ; U2.16@58.545,12.192 58.225,12.512 C3.2@55.626,12.512 53.782,12.512 52.857,13.437 C2.1@52.857,20.569 50.628,20.569 50.089,21.107 50.089,22.911 49.162,23.838
  Top Layer w0.7: L1.1@45.978,31.445 47.447,31.445 50.622,28.27 50.622,24.79 49.67,23.838
  Top Layer w0.8: v1@52.019,34.925 54.071,34.925 D12.1@54.604,35.458
  Bottom Layer w0.7: v1(52.095,34.9) 52.934,34.9 54.94,32.893 54.94,21.844 53.665,20.569 C2.1@52.857,20.569
  other v1: 52.883,34.95
+12V2: C8.1 C9.2 D3.2 J3.2 L2.1 R5.2 | length 30.2
  Top Layer w0.7: R5.2@78.522,24.521 78.522,24.17 79.731,22.962 83.363,22.962 L2.1@85.476,25.075 ; C9.2@84.938,16.967 85.476,17.506 C8.1@85.476,21.031 L2.1@85.476,25.075 ; C9.2@85.192,16.713 85.827,16.078 D3.2@85.827,14.478 87.115,13.189 J3.2@87.115,5.182 ; L2.1@86.055,25.654 L2.1@85.476,25.075
+12V3: C14.1 C15.2 D6.2 J5.2 L3.1 R11.2 | length 33.4
  Top Layer w0.8: R11.2@97.775,24.547 97.775,23.053 98.45,22.377 101.6,22.377 104.669,25.447 L3.1@106.172,25.447 106.172,23.667 C14.1@102.952,20.447 102.952,16.632 C15.2@102.88,16.561 102.88,15.072 D6.2@102.032,14.224 102.032,5.239 J5.2@101.974,5.182
+12V4: C61.1 C62.2 D11.2 J18.2 L6.1 R46.2 | length 40.6
  Top Layer w0.8: R46.2@113.144,35.128 113.144,33.896 114.148,32.893 L6.1@121.996,32.893 121.996,24.023 C61.1@121.646,23.673 121.646,19.198 C62.2@121.244,18.796 121.244,16.612 120.076,15.443 D11.2@119.482,15.443 119.482,7.602 J18.2@117.062,5.182
A1+: J2.1 U2.14 | length 13
  Top Layer w1: U2.14@58.545,17.272 60.833,14.984 J2.1@60.833,5.182
A1-: J2.2 U2.13 | length 17
  Top Layer w1: U2.13@58.545,19.812 59.182,19.812 63.373,15.621 J2.2@63.373,5.182
B1+: J2.3 U2.11 | length 22.8
  Top Layer w1: U2.11@58.545,24.892 65.913,17.524 J2.3@65.913,5.182
B1-: J2.4 U2.12 | length 22
  Bottom Layer w1: U2.12@58.545,22.352 59.817,22.352 68.453,13.716 J2.4@68.453,5.182
DIR: U2.8 U5.41 | length 62.7
  Top Layer w0.3: v1(73.279,51.13) 73.279,52.756 77.927,57.404 v1(77.927,57.785) ; U5.41@74.63,87.224 76.657,87.224 77.953,85.928 v1(77.953,72.898)
  Bottom Layer w0.3: U2.8@71.045,29.972 73.33,32.256 73.33,51.079 v1(73.279,51.13) ; v1(77.927,57.785) 77.953,57.81 v1(77.953,72.898)
EARTH: CY1.2 J9.3 | length 11.2
  Top Layer w1.5: J9.3@13.767,80.589 16.362,83.185 22.761,83.185 CY1.2@23.546,82.4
